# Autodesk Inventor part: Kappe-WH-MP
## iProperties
Shininess: 64.0
Length Units: 11269
Angle Units: 11279
Time Units: 11290
Mass Units: 11283
Length Display Precision: 3
Angle Display Precision: 2
Compacted: True
Part Number: Kappe-WH-MP
Document SubType Name: Modeling
Created: 2003-09
Material: Standard
Designer: W. Holzwarth
Density: 0.0
Volumn: 0.0
Area: 0.0
PropertySet Name: Model Information
Control State: 0
Master: False
Checked Out: False
Author: W. Holzwarth
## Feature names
1. Extrusion1
2. Extrusion2
3. Extrusion3
4. Extrusion4
5. Extrusion5
6. Rundung1 [Fillet]
7. Rundung3 [Fillet]
8. Rundung2 [Fillet]
